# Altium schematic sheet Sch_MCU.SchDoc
size A
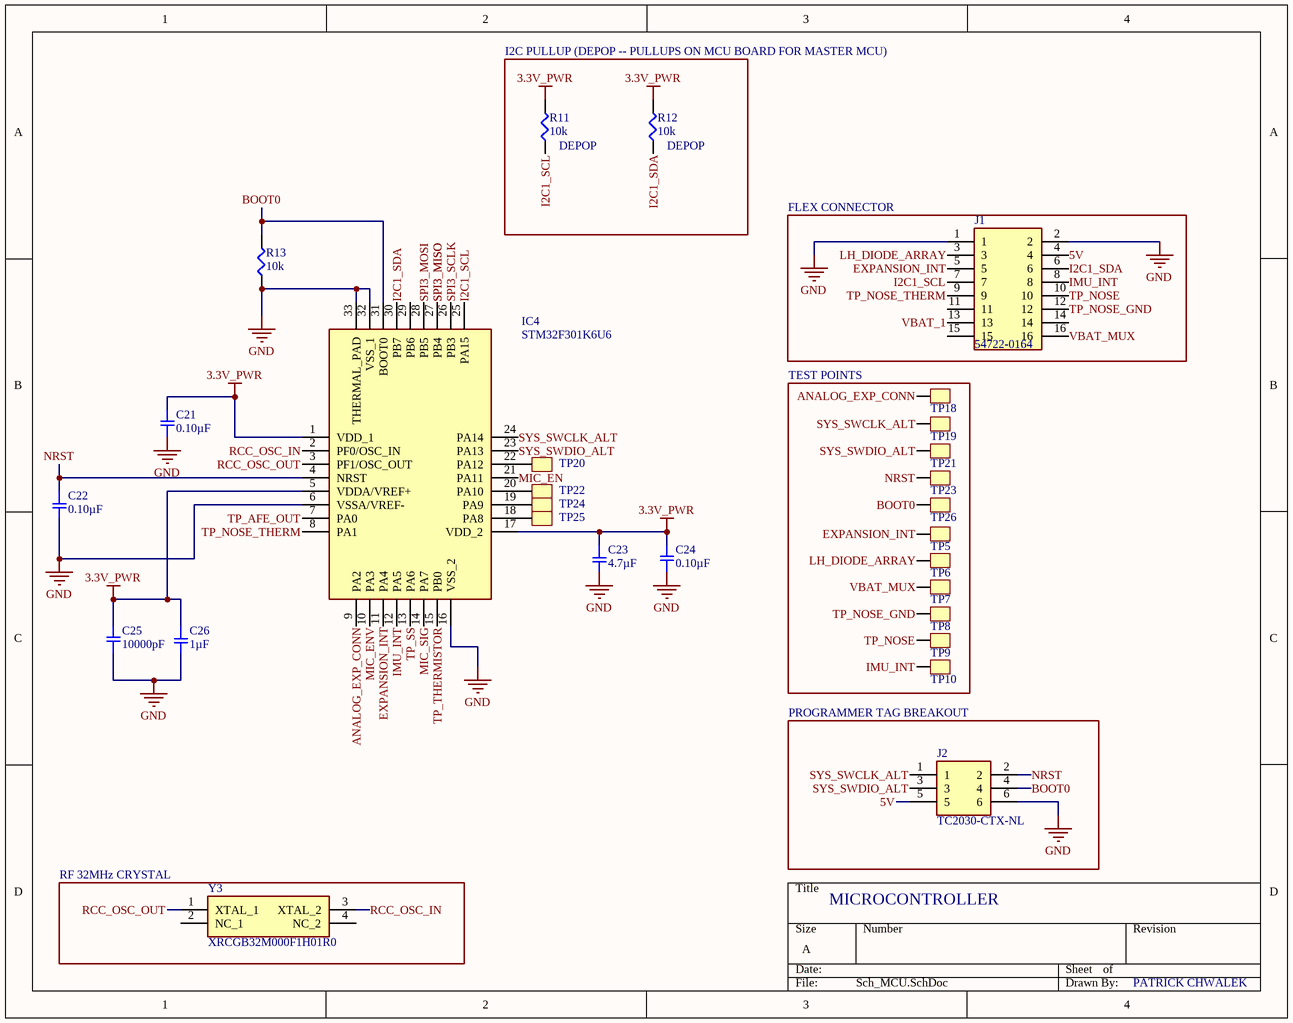
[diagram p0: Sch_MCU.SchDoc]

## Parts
C21  0.10µF  [SMD-0402C]
C22  0.10µF  [SMD-0402C]
C23  4.7µF  [SMD-0402C]
C24  0.10µF  [SMD-0402C]
C25  10000pF  [SMD-0402C]
C26  1µF  [SMD-0402C]
IC4  STM32F301K6U6  [QFN50P500X500X60-33N-D]
J1  54722-0164  [54722-0164]
J2  TC2030-CTX-NL  [TC2030MCPNL10]
R11  10k  [SMD-0402-RES]
R12  10k  [SMD-0402-RES]
R13  10k  [SMD-0402-RES]
TP5  TestPoint  [TestPoint_0.4mm]  (value not drawn)
TP6  TestPoint  [TestPoint_0.4mm]  (value not drawn)
TP7  TestPoint  [TestPoint_0.4mm]  (value not drawn)
TP8  TestPoint  [TestPoint_0.4mm]  (value not drawn)
TP9  TestPoint  [TestPoint_0.4mm]  (value not drawn)
TP10  TestPoint  [TestPoint_0.4mm]  (value not drawn)
TP18  TestPoint  [TestPoint_0.4mm]  (value not drawn)
TP19  TestPoint  [TestPoint_0.4mm]  (value not drawn)
TP20  TestPoint  [TESTPOINT_1MM_OVAL]  (value not drawn)
TP21  TestPoint  [TestPoint_0.4mm]  (value not drawn)
TP22  TestPoint  [TESTPOINT_1MM_OVAL]  (value not drawn)
TP23  TestPoint  [TestPoint_0.4mm]  (value not drawn)
TP24  TestPoint  [TESTPOINT_1MM_OVAL]  (value not drawn)
TP25  TestPoint  [TESTPOINT_1MM_OVAL]  (value not drawn)
TP26  TestPoint  [TestPoint_0.4mm]  (value not drawn)
Y3  XRCGB32M000F1H01R0  [XRCGB32M000F1H01R0]

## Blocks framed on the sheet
FLEX CONNECTOR: J1
TEST POINTS: TP5-TP10 TP18 TP19 TP21 TP23 TP26
PROGRAMMER TAG BREAKOUT: J2
RF 32MHz CRYSTAL: Y3

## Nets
3.3V_PWR: C21.2 C23.1 C24.2 C25.2 C26.1 IC4.1(VDD_1) IC4.5(VDDA/VREF+) IC4.17(VDD_2) R11.2 R12.2
GND: C21.1 C22.2 C23.2 C24.1 C25.1 C26.2 IC4.6(VSSA/VREF-) IC4.16(VSS_2) IC4.32(VSS_1) IC4.33(THERMAL_PAD) J1.1 J1.2 J2.6 R13.1
5V: J1.4 J2.5
ANALOG_EXP_CONN: IC4.9(PA2) TP18.1
BOOT0: IC4.31(BOOT0) J2.4 R13.2 TP26.1
EXPANSION_INT: IC4.11(PA4) J1.5 TP5.1
I2C1_SCL: IC4.25(PA15) J1.7 R11.1
I2C1_SDA: IC4.30(PB7) J1.6 R12.1
IMU_INT: IC4.12(PA5) J1.8 TP10.1
LH_DIODE_ARRAY: J1.3 TP6.1
MIC_EN: IC4.21(PA11)
MIC_ENV: IC4.10(PA3)
MIC_SIG: IC4.14(PA7)
NRST: C22.1 IC4.4(NRST) J2.2 TP23.1
RCC_OSC_IN: IC4.2(PF0/OSC_IN) Y3.3(XTAL_2)
RCC_OSC_OUT: IC4.3(PF1/OSC_OUT) Y3.1(XTAL_1)
SPI3_MISO: IC4.27(PB4)
SPI3_MOSI: IC4.28(PB5)
SPI3_SCLK: IC4.26(PB3)
SYS_SWCLK_ALT: IC4.24(PA14) J2.1 TP19.1
SYS_SWDIO_ALT: IC4.23(PA13) J2.3 TP21.1
TP_AFE_OUT: IC4.7(PA0)
TP_NOSE: J1.10 TP9.1
TP_NOSE_GND: J1.12 TP8.1
TP_NOSE_THERM: IC4.8(PA1) J1.9
TP_SS: IC4.13(PA6)
TP_THERMISTOR: IC4.15(PB0)
VBAT_1: J1.13
VBAT_MUX: J1.16 TP7.1
NetIC4_18: IC4.18(PA8) TP25.1
NetIC4_19: IC4.19(PA9) TP24.1
NetIC4_20: IC4.20(PA10) TP22.1
NetIC4_22: IC4.22(PA12) TP20.1

Not connected (* = marked no-connect by the designer): IC4 29(PB6); J1 11 14 15; Y3 2(NC_1) 4(NC_2)

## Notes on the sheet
- I2C PULLUP (DEPOP -- PULLUPS ON MCU BOARD FOR MASTER MCU)
- (near R11) DEPOP
- (near R12) DEPOP
- MICROCONTROLLER
- PATRICK CHWALEK

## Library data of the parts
C21 C22 C24 = GCM155R71C104KA55D: CAP CER 0.1UF 16V X7R 0402; Manufacturer: Murata Electronics North America; Factory Stock: 0; Unit Price (USD): 0.1; Minimum Quantity: 1; Tolerance: ±10%
C23 = GRM153R60G475ME15D: CAP CER 4.7UF 4V X5R 0402; Manufacturer: Murata Electronics North America; Factory Stock: 0; Unit Price (USD): 0.27; Minimum Quantity: 1; Tolerance: ±20%
C25 = GCM155R71H103KA55D: CAP CER 10000PF 50V X7R 0402; Manufacturer: Murata Electronics North America; Factory Stock: 0; Unit Price (USD): 0.1; Minimum Quantity: 1; Tolerance: ±10%
C26 = GCM155C71A105KE38D: CAP CER 1UF 10V X7S 0402; Manufacturer: Murata Electronics North America; Factory Stock: 0; Unit Price (USD): 0.12; Minimum Quantity: 1; Tolerance: ±10%
IC4 = STM32F301K6U6: Integrated Circuit; Manufacturer_Name: STMicroelectronics
J1 = 54722-0164: Connector; Manufacturer_Name: Molex
J2 = TC2030-CTX-NL: Connector; Manufacturer_Name: Tag Connect
R11-R13 = ERJ-2GEJ103X: RES SMD 10K OHM 5% 1/10W 0402; Manufacturer: Panasonic Electronic Components; Factory Stock: 0; Unit Price (USD): 0.00350; @ qty: 1500; Minimum Quantity: 1; Power (Watts): 0.1W, 1/10W; Temperature Coefficient: ±200ppm/°C
Y3 = XRCGB32M000F1H01R0: Crystal or Oscillator; Manufacturer_Name: Murata Electronics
